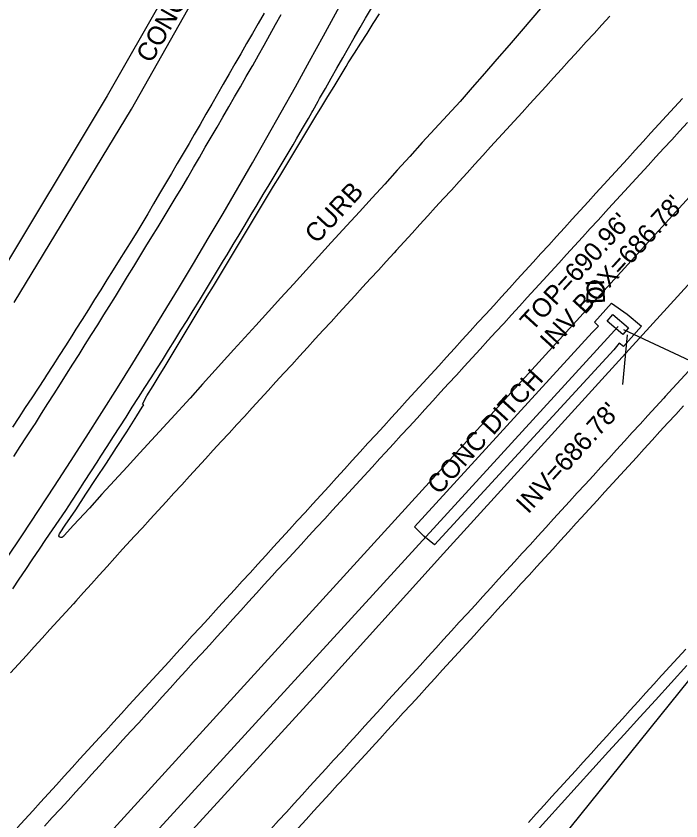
# Model space of a CAD drawing. Extents: x 1806071 to 1809844, y 912722 to 917035.
# Drawn here: x 1807440 to 1807582.5, y 914248.7 to 914421.2 of the extents above; entities that cross this region are included whole.
import ezdxf

# ---------------------------------------------------------------- set-up
doc = ezdxf.new("R2010")
doc.units = 0
for name, color, linetype in [('Exist Guardrail Cable Guide Rail', 7, 'Continuous'), ('Exist Horizontal Alignment', 7, 'Continuous'), ('Exist Roads Curbs', 7, 'Continuous'), ('Exist Roads Curbs Text', 7, 'Continuous'), ('Exist Roads EOP', 7, 'Continuous'), ('Exist Roads EOT', 7, 'Continuous'), ('Exist Structure Minor Drop Inlet', 7, 'Continuous'), ('Exist Structure Minor Drop Inlet Text', 7, 'Continuous'), ('Exist Structure Minor Drop Inlet Top Elevation', 7, 'Continuous'), ('Exist Structure Minor Paved Ditch or Gutter', 7, 'Continuous'), ('Exist Structure Minor Paved Ditch or Gutter Text', 7, 'Continuous'), ('Exist Structure Minor Pipes RCP 15 Inch', 7, 'Continuous'), ('Exist Structure Minor Pipes RCP 18 Inch Invert', 7, 'Continuous'), ('Exist Structure Minor Pipes RCP 24 Inch', 7, 'Continuous'), ('Exist Structure Minor Pipes RCP 24 Inch Invert', 7, 'Continuous')]:
    doc.layers.add(name, color=color, linetype=linetype)

msp = doc.modelspace()

# ---------------------------------------------------------------- linework, layer by layer
at = {"layer": 'Exist Guardrail Cable Guide Rail'}
msp.add_lwpolyline([(1807036.39, 913762.23), (1807072.19, 913801.95), (1807107.96, 913840.99), (1807141.41, 913877.77), (1807177.33, 913917.12), (1807208.48, 913951.28), (1807242.54, 913988.57), (1807278.56, 914027.99), (1807303.96, 914056.09), (1807333.75, 914088.73), (1807369.98, 914128.47), (1807402.65, 914164.36), (1807436.63, 914201.71), (1807469.41, 914237.65), (1807504.53, 914276.04), (1807531.63, 914306.03), (1807569.88, 914348.1), (1807608.39, 914390.29), (1807638.77, 914423.86), (1807675.81, 914465.75)], dxfattribs=at)
at = {"layer": 'Exist Horizontal Alignment'}
msp.add_line((1806073.69, 912724.84), (1809374.2, 916346.52), dxfattribs=at)
msp.add_arc((1806248.23, 915102.55), 1432.39, 321.65643, 337.65643, dxfattribs=at)
at = {"layer": 'Exist Roads Curbs'}
for points in [[(1807552.85, 914423.3), (1807548.27, 914418), (1807545.66, 914414.97), (1807543.05, 914411.95), (1807540.43, 914408.93), (1807537.79, 914405.92), (1807535.16, 914402.92), (1807532.46, 914399.98), (1807529.75, 914397.04), (1807527.07, 914394.08), (1807524.38, 914391.12), (1807521.7, 914388.15), (1807519.02, 914385.19), (1807516.33, 914382.23), (1807513.62, 914379.29), (1807510.94, 914376.32), (1807507.55, 914372.66), (1807504.86, 914369.71), (1807502.17, 914366.75), (1807499.49, 914363.79), (1807496.8, 914360.82), (1807494.11, 914357.88), (1807491.42, 914354.92), (1807486.7, 914349.76), (1807485.36, 914348.27), (1807482.68, 914345.3), (1807480, 914342.34), (1807477.34, 914339.36), (1807473.3, 914334.92), (1807466.53, 914327.58), (1807463.82, 914324.63), (1807458.43, 914318.73), (1807455.75, 914315.76), (1807452.38, 914312.08), (1807450.36, 914309.88), (1807450.24, 914309.76), (1807450.09, 914309.63), (1807449.96, 914309.52), (1807449.83, 914309.48), (1807449.66, 914309.46), (1807449.62, 914309.47), (1807449.41, 914309.55), (1807449.3, 914309.61), (1807449.23, 914309.81), (1807449.22, 914309.85), (1807449.26, 914310.05), (1807449.27, 914310.08), (1807449.35, 914310.27), (1807449.46, 914310.44), (1807450.58, 914312.11), (1807451.69, 914313.74), (1807452.82, 914315.4), (1807455.01, 914318.76), (1807457.18, 914322.1), (1807459.42, 914325.43), (1807461.58, 914328.78), (1807463.76, 914332.14), (1807465.89, 914335.53), (1807467.06, 914337.39), (1807467.38, 914337.9)], [(1807550.17, 914245.07), (1807553.55, 914248.75), (1807556.88, 914252.48), (1807560.24, 914256.18), (1807563.6, 914259.88), (1807566.95, 914263.59), (1807570.33, 914267.27), (1807573.68, 914270.98), (1807577.07, 914274.65), (1807580.39, 914278.36), (1807583.77, 914282.04)]]:
    msp.add_lwpolyline(points, dxfattribs=at)
at = {"layer": 'Exist Roads EOP'}
for points in [[(1807493.19, 914421.8), (1807491.94, 914419.64), (1807490.69, 914417.47), (1807489.44, 914415.31), (1807488.19, 914413.14), (1807486.94, 914410.97), (1807485.69, 914408.81), (1807484.44, 914406.64), (1807483.19, 914404.48), (1807481.95, 914402.31), (1807480.7, 914400.15), (1807479.45, 914397.98), (1807478.2, 914395.82), (1807477.11, 914393.93), (1807475.84, 914391.77), (1807474.57, 914389.62), (1807473.31, 914387.46), (1807472.04, 914385.31), (1807470.77, 914383.15), (1807469.51, 914381), (1807468.24, 914378.84), (1807466.97, 914376.69), (1807466.14, 914375.28), (1807464.82, 914373.16), (1807463.49, 914371.04), (1807462.16, 914368.92), (1807460.84, 914366.8), (1807459.51, 914364.68), (1807458.18, 914362.56), (1807456.86, 914360.45), (1807455.53, 914358.33), (1807454.2, 914356.21), (1807452.88, 914354.09), (1807451.98, 914352.65), (1807450.63, 914350.54), (1807449.28, 914348.44), (1807447.93, 914346.33), (1807446.58, 914344.23), (1807446.14, 914343.55), (1807444.76, 914341.47), (1807443.39, 914339.38), (1807442.01, 914337.3), (1807440.63, 914335.21), (1807439.25, 914333.12)], [(1807467.38, 914337.9), (1807467.12, 914338.06), (1807468.09, 914339.8), (1807469.38, 914341.94), (1807470.68, 914344.08), (1807471.97, 914346.22), (1807473.26, 914348.36), (1807474.55, 914350.5), (1807475.85, 914352.64), (1807477.14, 914354.78), (1807478.43, 914356.92), (1807479.72, 914359.06), (1807481.01, 914361.2), (1807482.31, 914363.34), (1807483.6, 914365.48), (1807484.89, 914367.62), (1807486.18, 914369.76), (1807487.48, 914371.9), (1807488.77, 914374.04), (1807490.06, 914376.18), (1807491.35, 914378.32), (1807492.65, 914380.46), (1807493.94, 914382.6), (1807495.23, 914384.74), (1807496.52, 914386.88), (1807497.82, 914389.02), (1807499.11, 914391.16), (1807500.4, 914393.3), (1807501.69, 914395.44), (1807502.99, 914397.58), (1807504.28, 914399.72), (1807505.57, 914401.86), (1807506.86, 914404), (1807508.16, 914406.14), (1807509.45, 914408.28), (1807510.74, 914410.42), (1807511.2, 914411.17), (1807512.54, 914413.28), (1807513.88, 914415.39), (1807515.23, 914417.5), (1807516.57, 914419.61), (1807517.91, 914421.71)], [(1807446.13, 914247.59), (1807447.81, 914249.44), (1807449.49, 914251.29), (1807451.17, 914253.14), (1807452.85, 914254.99), (1807454.54, 914256.84), (1807456.22, 914258.69), (1807457.9, 914260.54), (1807459.58, 914262.39), (1807461.26, 914264.24), (1807462.95, 914266.09), (1807464.63, 914267.94), (1807466.31, 914269.79), (1807467.99, 914271.64), (1807469.67, 914273.49), (1807471.36, 914275.34), (1807473.04, 914277.19), (1807474.72, 914279.04), (1807476.4, 914280.89), (1807478.08, 914282.74), (1807479.77, 914284.58), (1807481.45, 914286.43), (1807483.13, 914288.28), (1807484.81, 914290.13), (1807486.49, 914291.98), (1807488.18, 914293.83), (1807489.86, 914295.68), (1807491.54, 914297.53), (1807493.22, 914299.38), (1807494.9, 914301.23), (1807496.01, 914302.45), (1807497.71, 914304.29), (1807499.4, 914306.13), (1807501.09, 914307.97), (1807502.78, 914309.81), (1807504.47, 914311.66), (1807506.16, 914313.5), (1807507.86, 914315.34), (1807509.55, 914317.18), (1807511.24, 914319.02), (1807512.93, 914320.86), (1807514.62, 914322.7), (1807516.32, 914324.54), (1807518.01, 914326.38), (1807519.2, 914327.68), (1807520.89, 914329.53), (1807522.58, 914331.37), (1807524.26, 914333.22), (1807525.95, 914335.06), (1807527.64, 914336.91), (1807529.32, 914338.75), (1807531.01, 914340.6), (1807532.7, 914342.44), (1807534.38, 914344.29), (1807536.07, 914346.14), (1807537.76, 914347.98), (1807539.44, 914349.83), (1807541.13, 914351.67), (1807542.82, 914353.52), (1807544.51, 914355.36), (1807546.19, 914357.21), (1807547.88, 914359.05), (1807549.57, 914360.9), (1807551.25, 914362.74), (1807552.94, 914364.59), (1807554.63, 914366.43), (1807556.31, 914368.28), (1807558, 914370.12), (1807559.69, 914371.97), (1807561.37, 914373.81), (1807563.06, 914375.66), (1807564.75, 914377.5), (1807566.43, 914379.35), (1807567, 914379.97), (1807568.69, 914381.81), (1807570.38, 914383.66), (1807572.07, 914385.5), (1807573.76, 914387.34), (1807575.45, 914389.18), (1807577.14, 914391.03), (1807578.83, 914392.87), (1807580.52, 914394.71), (1807582.21, 914396.55), (1807583.9, 914398.4)], [(1807584.15, 914345.18), (1807582.46, 914343.34), (1807580.78, 914341.49), (1807579.09, 914339.65), (1807578.8, 914339.33), (1807577.12, 914337.48), (1807575.43, 914335.64), (1807573.75, 914333.79), (1807572.07, 914331.94), (1807570.38, 914330.09), (1807568.7, 914328.25), (1807567.01, 914326.4), (1807565.33, 914324.55), (1807563.65, 914322.7), (1807561.96, 914320.86), (1807560.28, 914319.01), (1807558.59, 914317.16), (1807556.91, 914315.31), (1807555.22, 914313.47), (1807553.54, 914311.62), (1807551.86, 914309.77), (1807550.17, 914307.92), (1807548.49, 914306.08), (1807546.8, 914304.23), (1807545.12, 914302.38), (1807543.43, 914300.53), (1807541.75, 914298.69), (1807540.07, 914296.84), (1807538.38, 914294.99), (1807536.7, 914293.14), (1807535.01, 914291.3), (1807533.33, 914289.45), (1807531.64, 914287.6), (1807529.96, 914285.75), (1807528.28, 914283.91), (1807526.59, 914282.06), (1807524.91, 914280.21), (1807523.22, 914278.36), (1807521.54, 914276.52), (1807519.85, 914274.67), (1807518.17, 914272.82), (1807516.49, 914270.97), (1807514.8, 914269.13), (1807513.12, 914267.28), (1807511.43, 914265.43), (1807509.75, 914263.58), (1807508.07, 914261.74), (1807506.38, 914259.89), (1807504.7, 914258.04), (1807503.01, 914256.19), (1807501.33, 914254.35), (1807499.64, 914252.5), (1807497.96, 914250.65), (1807496.28, 914248.8), (1807494.59, 914246.96)], [(1807549.81, 914248.38), (1807551.48, 914250.24), (1807553.16, 914252.09), (1807554.84, 914253.94), (1807556.52, 914255.8), (1807558.19, 914257.65), (1807559.87, 914259.51), (1807561.55, 914261.36), (1807563.23, 914263.21), (1807564.91, 914265.07), (1807566.58, 914266.92), (1807568.26, 914268.77), (1807569.94, 914270.63), (1807571.62, 914272.48), (1807573.29, 914274.33), (1807574.97, 914276.19), (1807576.65, 914278.04), (1807578.33, 914279.9), (1807578.44, 914280.02), (1807580.14, 914281.86), (1807581.83, 914283.7), (1807583.52, 914285.54)]]:
    msp.add_lwpolyline(points, dxfattribs=at)
at = {"layer": 'Exist Roads EOT'}
for points in [[(1807439.34, 914298.48), (1807440.73, 914300.55), (1807442.12, 914302.63), (1807443.51, 914304.71), (1807443.65, 914304.91), (1807445.05, 914306.98), (1807446.45, 914309.04), (1807447.86, 914311.11), (1807449.26, 914313.18), (1807450.67, 914315.24), (1807452.02, 914317.24), (1807453.37, 914319.35), (1807454.73, 914321.45), (1807456.08, 914323.55), (1807457.43, 914325.65), (1807458.21, 914326.87), (1807459.56, 914328.97), (1807460.9, 914331.08), (1807462.25, 914333.18), (1807463.6, 914335.29), (1807464.94, 914337.39), (1807466.29, 914339.5), (1807467.63, 914341.6), (1807468.98, 914343.71), (1807470.33, 914345.81), (1807471.41, 914347.5), (1807472.73, 914349.62), (1807474.05, 914351.75), (1807475.37, 914353.87), (1807476.69, 914355.99), (1807478, 914358.12), (1807479.33, 914360.25), (1807480.63, 914362.39), (1807481.92, 914364.52), (1807483.22, 914366.66), (1807484.51, 914368.8), (1807485.29, 914370.07), (1807486.57, 914372.22), (1807487.86, 914374.36), (1807489.14, 914376.5), (1807490.42, 914378.65), (1807491.71, 914380.79), (1807492.99, 914382.94), (1807494.25, 914385.04), (1807495.53, 914387.18), (1807496.81, 914389.33), (1807498.1, 914391.48), (1807499.38, 914393.62), (1807500.15, 914394.92), (1807501.4, 914397.08), (1807502.66, 914399.25), (1807503.39, 914400.51), (1807503.61, 914400.92), (1807504.75, 914402.97), (1807505.08, 914403.54), (1807506.32, 914405.71), (1807507.56, 914407.88), (1807508.8, 914410.05), (1807510.04, 914412.22), (1807511.28, 914414.39), (1807512.51, 914416.57), (1807513.75, 914418.74), (1807514.91, 914420.74), (1807516.17, 914422.9)], [(1807567.26, 914421.2), (1807565.57, 914419.35), (1807563.89, 914417.5), (1807562.21, 914415.65), (1807560.52, 914413.8), (1807558.84, 914411.96), (1807558.56, 914411.65), (1807556.87, 914409.8), (1807555.19, 914407.95), (1807553.51, 914406.1), (1807551.82, 914404.26), (1807550.14, 914402.41), (1807548.45, 914400.56), (1807546.77, 914398.71), (1807545.09, 914396.87), (1807543.4, 914395.02), (1807541.72, 914393.17), (1807540.03, 914391.32), (1807538.35, 914389.47), (1807536.67, 914387.63), (1807534.98, 914385.78), (1807533.3, 914383.93), (1807531.62, 914382.08), (1807529.93, 914380.23), (1807528.25, 914378.39), (1807526.56, 914376.54), (1807524.88, 914374.69), (1807523.2, 914372.84), (1807521.51, 914370.99), (1807521.03, 914370.47), (1807519.35, 914368.63), (1807517.66, 914366.78), (1807515.97, 914364.94), (1807514.28, 914363.09), (1807512.59, 914361.25), (1807510.9, 914359.41), (1807509.22, 914357.56), (1807507.53, 914355.72), (1807505.84, 914353.87), (1807504.15, 914352.03), (1807502.46, 914350.19), (1807500.78, 914348.34), (1807499.09, 914346.5), (1807497.4, 914344.65), (1807495.71, 914342.81), (1807494.02, 914340.97), (1807492.34, 914339.12), (1807490.65, 914337.28), (1807488.96, 914335.43), (1807487.37, 914333.69), (1807485.68, 914331.85), (1807483.99, 914330.01), (1807482.3, 914328.16), (1807480.61, 914326.32), (1807478.92, 914324.48), (1807477.23, 914322.63), (1807475.55, 914320.79), (1807473.86, 914318.94), (1807472.17, 914317.1), (1807470.48, 914315.26), (1807468.79, 914313.41), (1807467.1, 914311.57), (1807465.41, 914309.73), (1807463.72, 914307.88), (1807462.88, 914306.97), (1807461.21, 914305.11), (1807459.54, 914303.25), (1807457.86, 914301.4), (1807456.19, 914299.54), (1807454.51, 914297.68), (1807452.84, 914295.83), (1807452.35, 914295.29), (1807450.67, 914293.44), (1807448.98, 914291.59), (1807447.3, 914289.74), (1807445.62, 914287.89), (1807443.93, 914286.04), (1807442.25, 914284.2), (1807440.57, 914282.35), (1807438.88, 914280.5)], [(1807439.58, 914326.86), (1807440.94, 914328.96), (1807442.31, 914331.05), (1807443.68, 914333.15), (1807444.19, 914333.93), (1807445.52, 914336.04), (1807446.86, 914338.16), (1807448.19, 914340.27), (1807449.53, 914342.38), (1807450.86, 914344.5), (1807452.2, 914346.61), (1807453.53, 914348.72), (1807454.87, 914350.84), (1807456.2, 914352.95), (1807457.54, 914355.07), (1807458.87, 914357.18), (1807460.02, 914359), (1807461.33, 914361.13), (1807462.63, 914363.26), (1807463.94, 914365.4), (1807465.24, 914367.53), (1807466.54, 914369.66), (1807467.85, 914371.8), (1807469.15, 914373.93), (1807470.46, 914376.06), (1807471.76, 914378.19), (1807473.06, 914380.33), (1807474.37, 914382.46), (1807475.57, 914384.43), (1807476.83, 914386.59), (1807478.08, 914388.75), (1807479.33, 914390.92), (1807480.59, 914393.08), (1807481.84, 914395.24), (1807483.1, 914397.41), (1807484.35, 914399.57), (1807485.6, 914401.73), (1807486.86, 914403.89), (1807488.11, 914406.06), (1807489.37, 914408.22), (1807490.62, 914410.38), (1807490.76, 914410.62), (1807491.97, 914412.81), (1807493.18, 914415), (1807494.39, 914417.19), (1807495.6, 914419.38), (1807496.81, 914421.57)], [(1807440.25, 914247.23), (1807441.93, 914249.08), (1807443.61, 914250.93), (1807445.3, 914252.78), (1807446.98, 914254.62), (1807448.67, 914256.47), (1807450.35, 914258.32), (1807452.03, 914260.17), (1807453.72, 914262.02), (1807455.4, 914263.87), (1807457.08, 914265.71), (1807458.77, 914267.56), (1807459.24, 914268.08), (1807460.93, 914269.93), (1807462.62, 914271.77), (1807464.3, 914273.62), (1807465.99, 914275.46), (1807467.68, 914277.31), (1807469.37, 914279.15), (1807471.05, 914281), (1807472.74, 914282.84), (1807474.43, 914284.68), (1807476.12, 914286.53), (1807477.8, 914288.37), (1807479.49, 914290.22), (1807481.18, 914292.06), (1807482.87, 914293.91), (1807483.44, 914294.54), (1807485.13, 914296.39), (1807486.81, 914298.23), (1807488.5, 914300.08), (1807490.18, 914301.93), (1807491.86, 914303.78), (1807493.55, 914305.62), (1807495.23, 914307.47), (1807496.92, 914309.32), (1807498.6, 914311.17), (1807500.28, 914313.02), (1807501.97, 914314.86), (1807503.65, 914316.71), (1807505.34, 914318.56), (1807507.02, 914320.41), (1807508.7, 914322.25), (1807510.39, 914324.1), (1807512.07, 914325.95), (1807513.75, 914327.8), (1807515.44, 914329.65), (1807517.12, 914331.49), (1807518.81, 914333.34), (1807520.49, 914335.19), (1807522.17, 914337.04), (1807523.86, 914338.88), (1807525.54, 914340.73), (1807527.23, 914342.58), (1807528.91, 914344.43), (1807530.59, 914346.28), (1807532.28, 914348.12), (1807533.96, 914349.97), (1807535.65, 914351.82), (1807537.33, 914353.67), (1807539.01, 914355.51), (1807540.7, 914357.36), (1807542.38, 914359.21), (1807544.07, 914361.06), (1807545.75, 914362.91), (1807547.43, 914364.75), (1807549.12, 914366.6), (1807550.8, 914368.45), (1807552.49, 914370.3), (1807554.17, 914372.14), (1807555.85, 914373.99), (1807557.54, 914375.84), (1807559.22, 914377.69), (1807560.91, 914379.54), (1807562.59, 914381.38), (1807564.27, 914383.23), (1807565.96, 914385.08), (1807567.64, 914386.93), (1807569.33, 914388.77), (1807571.01, 914390.62), (1807572.69, 914392.47), (1807574.38, 914394.32), (1807576.06, 914396.17), (1807577.74, 914398.01), (1807579.43, 914399.86), (1807581.11, 914401.71), (1807582.8, 914403.56)], [(1807583.05, 914337.71), (1807581.36, 914335.86), (1807579.68, 914334.01), (1807577.99, 914332.17), (1807576.31, 914330.32), (1807574.62, 914328.47), (1807572.94, 914326.63), (1807571.25, 914324.78), (1807569.57, 914322.93), (1807567.88, 914321.09), (1807566.2, 914319.24), (1807564.51, 914317.39), (1807562.83, 914315.55), (1807561.14, 914313.7), (1807560.06, 914312.52), (1807558.38, 914310.67), (1807556.7, 914308.82), (1807555.01, 914306.97), (1807553.33, 914305.13), (1807551.64, 914303.28), (1807549.96, 914301.43), (1807548.27, 914299.58), (1807546.59, 914297.74), (1807544.91, 914295.89), (1807543.22, 914294.04), (1807541.54, 914292.19), (1807539.85, 914290.35), (1807538.17, 914288.5), (1807536.48, 914286.65), (1807534.8, 914284.8), (1807533.12, 914282.96), (1807531.43, 914281.11), (1807529.75, 914279.26), (1807528.06, 914277.41), (1807526.38, 914275.57), (1807524.7, 914273.72), (1807523.01, 914271.87), (1807521.33, 914270.02), (1807519.64, 914268.18), (1807517.96, 914266.33), (1807516.27, 914264.48), (1807515.67, 914263.82), (1807513.98, 914261.97), (1807512.3, 914260.13), (1807510.61, 914258.28), (1807508.92, 914256.44), (1807507.23, 914254.59), (1807505.55, 914252.74), (1807503.86, 914250.9), (1807502.17, 914249.05), (1807500.49, 914247.21)]]:
    msp.add_lwpolyline(points, dxfattribs=at)
at = {"layer": 'Exist Structure Minor Drop Inlet'}
msp.add_lwpolyline([(1807567.91, 914357.24), (1807571.22, 914354.38), (1807570.02, 914353), (1807566.71, 914355.85)], close=True, dxfattribs=at)
at = {"layer": 'Exist Structure Minor Paved Ditch or Gutter'}
for points in [[(1807546.15, 914577.54), (1807529.9, 914539.49), (1807502.29, 914479.4), (1807483.96, 914446.87), (1807459.55, 914404.11), (1807434.92, 914363.15), (1807436.63, 914361.7)], [(1807439.65, 914359.8), (1807464.74, 914401.26), (1807489.22, 914444.52), (1807506.17, 914478.05), (1807534.83, 914536.85), (1807551.23, 914575.61)], [(1807564.85, 914354.78), (1807563.94, 914355.6), (1807567.62, 914359.68), (1807571, 914357.3), (1807574.07, 914354.73), (1807570.15, 914350.39), (1807569.25, 914351.08)], [(1807527.44, 914309.79), (1807525.37, 914311.73), (1807563.45, 914353.41), (1807564.85, 914354.78)], [(1807569.25, 914351.08), (1807568.12, 914349.65), (1807529.7, 914307.88), (1807527.44, 914309.79)]]:
    msp.add_lwpolyline(points, dxfattribs=at)
at = {"layer": 'Exist Structure Minor Pipes RCP 15 Inch'}
msp.add_line((1807426.13, 914082.91), (1807623.11, 914327.12), dxfattribs=at)
at = {"layer": 'Exist Structure Minor Pipes RCP 24 Inch'}
for p, q in [((1807298.31, 914058.62), (1807569.06, 914354.69)), ((1807570.17, 914354.03), (1807624.11, 914328.83))]:
    msp.add_line(p, q, dxfattribs=at)
at = {"layer": 'Exist Structure Minor Pipes RCP 24 Inch Invert'}
msp.add_line((1807570.98, 914352.92), (1807569.99, 914342.29), dxfattribs=at)

# ---------------------------------------------------------------- texts
at = {"layer": 'Exist Roads Curbs Text'}
msp.add_text('CURB', height=4, rotation=47.2627, dxfattribs=at).set_placement((1807504.44, 914372.24))
at = {"layer": 'Exist Structure Minor Drop Inlet Text'}
msp.add_text('DI', height=4, rotation=92.8422, dxfattribs=at).set_placement((1807566.27, 914359.56))
at = {"layer": 'Exist Structure Minor Drop Inlet Top Elevation'}
msp.add_text("TOP=690.96'", height=4, rotation=47.5262, dxfattribs=at).set_placement((1807550.61, 914353.48))
at = {"layer": 'Exist Structure Minor Paved Ditch or Gutter Text'}
for rotation, p in [(60.276, (1807469.01, 914410.9)), (47.7051, (1807530.66, 914318.45))]:
    msp.add_text('CONC DITCH', height=4, rotation=rotation, dxfattribs=at).set_placement(p)
at = {"layer": 'Exist Structure Minor Pipes RCP 18 Inch Invert'}
msp.add_text("INV BOX=686.78'", height=4, rotation=47.5262, dxfattribs=at).set_placement((1807554.87, 914349.42))
at = {"layer": 'Exist Structure Minor Pipes RCP 24 Inch Invert'}
msp.add_text("INV=686.78'", height=4, rotation=47.677, dxfattribs=at).set_placement((1807549.76, 914314.36))

doc.saveas('drawing.dxf')
